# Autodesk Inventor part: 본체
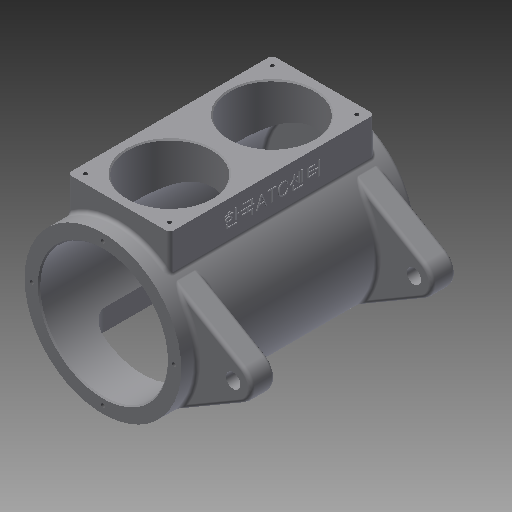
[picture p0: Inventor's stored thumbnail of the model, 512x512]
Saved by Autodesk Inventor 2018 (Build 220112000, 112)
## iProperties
Created: 2016-11
Part Number: 본체
Material: 일반
Document SubType Name: Modeling
Designer: mduedu
Density: 1 g/cm^3
Appearance: 기본값
Author: mduedu
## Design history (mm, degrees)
sketch "스케치1"
  geometry: C1 r 65 at (0, 0); 1 further point
  constraints: 1 centre point, 1 coincident
  dimensions: "d119" = 130 diameter of C1
extrude "돌출1" new body sketch "스케치1" distance "d3" = 98; taper "d4" = 0 deg; dims "d132" = 97, "d133" = 0
feature "쉘1" dims "d120" = 12, "d134" = 8
node "작업 평면2"
sketch "스케치13"
  geometry: L1 (42.5, 85)-(-42.5, 85); L2 (-42.5, 85)-(-42.5, -85); L3 (-42.5, -85)-(42.5, -85); L4 (42.5, -85)-(42.5, 85); 2 further points
  constraints: 8 end point, 2 parallel, 1 horizontal, 1 midpoint, 1 perpendicular, 1 vertical alignment
  dimensions: "d122" = 170 distance of L1.end L2.end; "d124" = 85 distance of L2.end L3.end; "d125" = 85 distance from line of point (0, 0) L1 (= 0.5 x d122)
extrude "돌출11" join sketch "스케치13" stored distance "d126" = 10; taper "d127" = 0 deg
sketch "스케치14"
  geometry: L1 (65, 97)-(-65, 97) reference; C1 r 35 at (0, 42.5); 1 further point
  constraints: 1 centre point, 1 vertical alignment
  dimensions: "d128" = 70 diameter of C1; "d129" = 54.5 distance from line of C1.centre L1
extrude "돌출12" cut sketch "스케치14" stored distance "d130" = 10; taper "d131" = 0 deg
sketch "스케치15"
  geometry: C1 r 53 at (0, 0) reference; 1 further point
extrude "돌출13" cut sketch "스케치15" stored distance "d135" = 10; taper "d136" = 0 deg
chamfer "모따기1" distance "d54" = 1; stored, may be unused: second distance "d55" = 2, angle "d56" = 45 deg
sketch "스케치8"
  geometry: C1 r 23 at (0, 0); C2 r 65 at (0, 0) reference; 1 further point
  constraints: 1 centre point, 1 concentric
  dimensions: "d57" = 46 diameter of C1
extrude "돌출8" join sketch "스케치8" distance "d58" = 14; taper "d59" = 0 deg
feature "면 기울기1" dims angle "d202" = 10 deg
hole "구멍3" diameter "d62" = 24; stored, may be unused: countersink angle "d66" = 90 deg, drill point angle "d68" = 0 deg; dims "d63" = 6, "d64" = 28, "d65" = 8, "d67" = 14, "d169" = 10, "d170" = 10
fillet "모깎기11" dims "d69" = 3
fillet "모깎기12" dims "d70" = 3
fillet "모깎기13" dims "d71" = 0.3
chamfer "모따기2" distance "d72" = 1; stored, may be unused: second distance "d73" = 2, angle "d74" = 45 deg
node "작업 평면3"
sketch "스케치16"
  geometry: L1 (-42.5, -80)-(52.5, -80); L2 (-42.5, -80)-(24.675, -12.825); L3 (-42.5, -80)-(24.675, -147.175); L4 (3.462, -34.038)-(60.057, -67.042); L5 (3.462, -125.962)-(60.057, -92.958); A1 r 65 centre (-42.5, -80) between (3.462, -34.038) and (3.462, -125.962) reference; A2 r 65 centre (-42.5, -80) between (3.462, -125.962) and (3.462, -34.038); A3 r 95 centre (-42.5, -80) between (52.5, -80) and (24.675, -147.175); A4 r 15 centre (52.5, -80) between (60.057, -67.042) and (60.057, -92.958); 1 further point
  constraints: 10 end point, 9 point on circle, 3 centre point, 3 coincident, 2 point on line, 2 tangent, 1 horizontal
  dimensions: "d140" = 45 deg angle of L3 L1; "d141" = 45 deg angle of L2 L1; "d194" = 30 radial gap between concentric circles of A3 A1; "d195" = 30 diameter of A4
extrude "돌출14" join sketch "스케치16" distance "d143" = 20; taper "d144" = 0 deg
fillet "모깎기25" dims "d196" = 3
fillet "모깎기26" dims "d197" = 3
sketch "스케치22"
  geometry: C1 r 6 at (52.5, -80); A1 r 15 centre (52.5, -80) between (60.057, -92.958) and (60.057, -67.042) reference; 1 further point
  constraints: 1 centre point, 1 coincident
  dimensions: "d198" = 12 diameter of C1
extrude "돌출17" cut sketch "스케치22" extent not by distance; stored distance "d200" = 10; taper "d201" = 0 deg
fillet "모깎기20" dims "d159" = 3
fillet "모깎기21" dims "d160" = 3
fillet "모깎기22" dims "d161" = 3
node "작업 평면4"
sketch "스케치18"
  geometry: L1 (-42.5, 65)-(42.5, 65); L2 (42.5, 65)-(42.5, -65); L3 (42.5, -65)-(-42.5, -65); L4 (-42.5, -65)-(-42.5, 65); 2 further points
  constraints: 8 end point, 2 parallel, 1 horizontal, 1 midpoint, 1 perpendicular, 1 vertical alignment
  dimensions: "d162" = 130 distance of L1.end L2.end; "d164" = 85 distance of L2.end L3.end; "d165" = 65 distance from line of point (0, 0) L1 (= 0.5 x d162)
extrude "돌출16" cut sketch "스케치18" stored distance "d166" = 15; taper "d167" = 0 deg; dims "d73" = 2
fillet "모깎기23" dims "d168" = 10
fillet "모깎기24" dims "d173" = 3
sketch "스케치19"
  geometry: 4 further points
  constraints: 4 other
hole "구멍6" sketch "스케치19" at (0, -59), (59, 0), (-59, 0), (0, 59) diameter "d174" = 3.242; stored, may be unused: countersink angle "d178" = 90 deg, drill point angle "d180" = 120 deg; dims "d175" = 7, "d176" = 4, "d177" = 2, "d179" = 9
sketch "스케치20"
  geometry: L1 (35, -77.5)-(-35, -77.5); L2 (-35, -77.5)-(-35, -7.5); L3 (-35, -7.5)-(35, -7.5); L4 (35, -7.5)-(35, -77.5); L5 (35, -77.5)-(-35, -7.5); L6 (-35, -77.5)-(35, -7.5); C1 r 36 at (0, -42.5) reference; 3 further points
  constraints: 12 end point, 2 coincident, 2 midpoint, 2 parallel, 1 horizontal, 1 perpendicular
  dimensions: "d181" = 70 distance of L2.end L3.end; "d182" = 70 distance of L1.end L2.end
hole "구멍7" sketch "스케치20" at (-35, -77.5), (35, -77.5) diameter "d183" = 3.242; stored, may be unused: countersink angle "d187" = 90 deg, drill point angle "d189" = 118 deg; dims "d184" = 7, "d185" = 4, "d186" = 2, "d188" = 9
sketch "스케치21"
  geometry: L1 (164, 0)-(0, 0) reference; L2 (-3, 0)-(-3, -24.649) reference; 3 further points
  constraints: 1 midpoint, 1 vertical alignment, 1 other
  dimensions: "d190" = 15 distance from line of point (82, -15) L1; "d191" = 85 distance from line of point (82, 0) L2 (derived)
feature "엠보싱2" sketch "스케치21" dims "d119" = 130, "d192" = 0.5, "d193" = 0
node "솔리드1"
mirror "대칭5"
mirror "대칭6"
mirror "대칭7"
